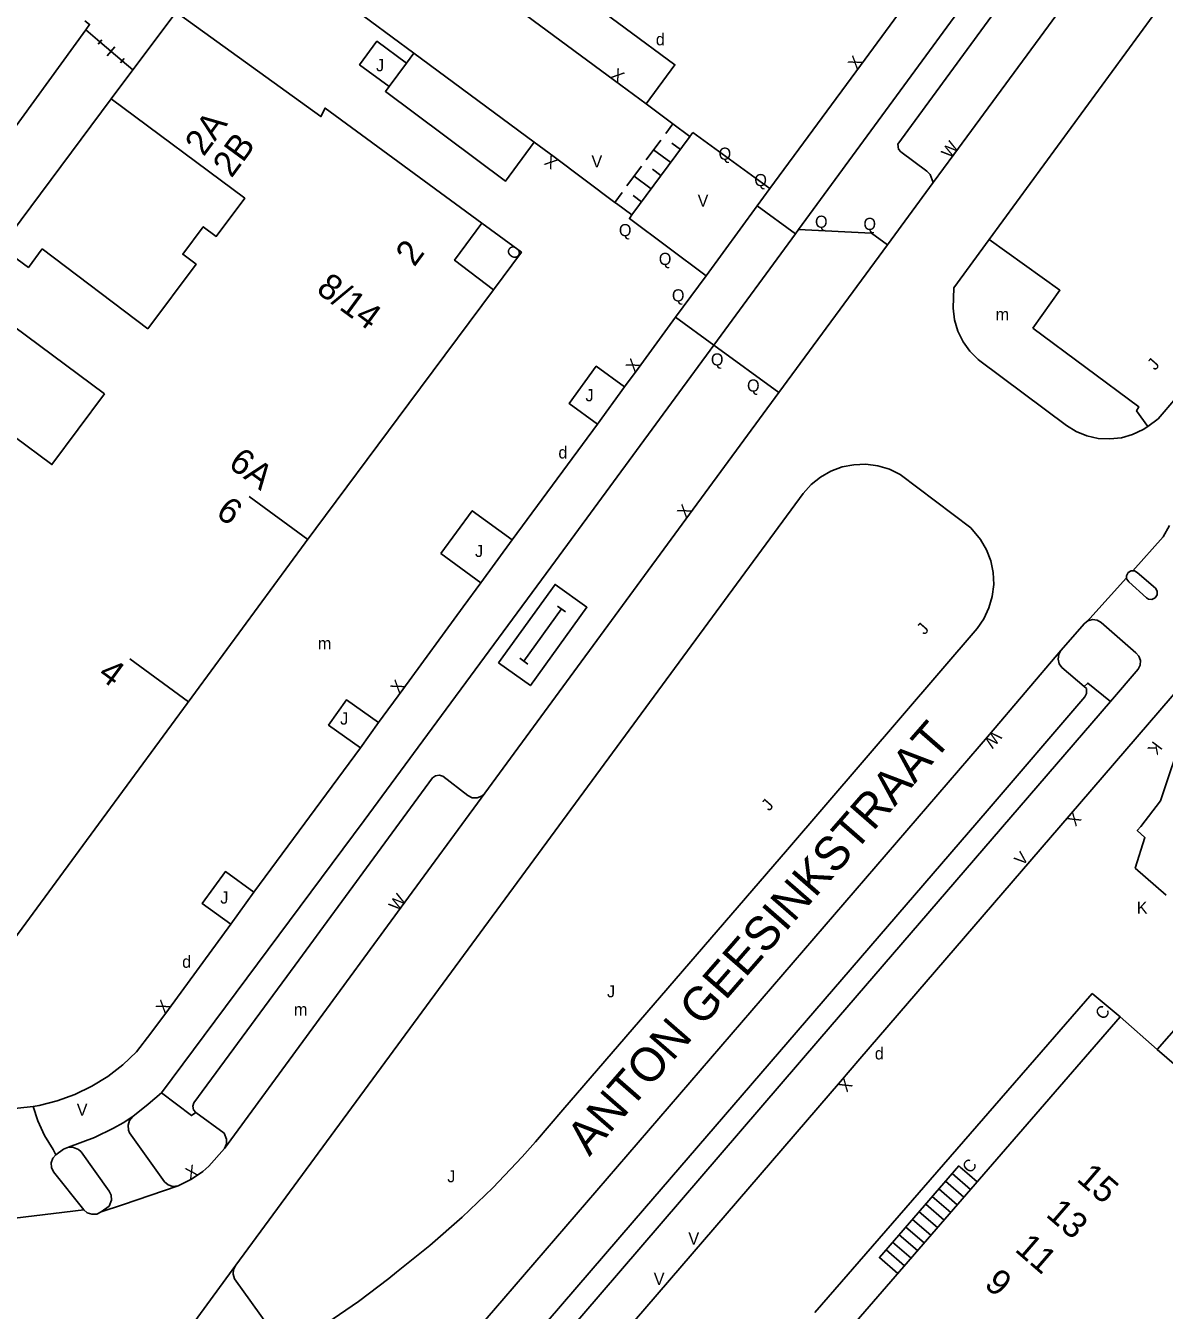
# Model space of a CAD drawing. Extents: x 134999 to 136502, y 457398 to 459002.
# Drawn here: x 135720.5 to 135767.4, y 457512.2 to 457565.2 of the extents above; entities that cross this region are included whole.
import ezdxf

# ---------------------------------------------------------------- set-up
doc = ezdxf.new("R2010")
doc.units = 0
for name, color, linetype in [('RI_DGTB_15', 7, 'Continuous'), ('RI_DGTB_2', 7, 'Continuous'), ('RI_DGTB_28', 7, 'Continuous'), ('RI_DGTB_29', 7, 'Continuous'), ('RI_DGTB_30', 7, 'Continuous'), ('RI_DGTB_31', 7, 'Continuous'), ('RI_DGTB_35', 7, 'Continuous'), ('RI_DGTB_36', 7, 'Continuous'), ('RI_DGTB_37', 7, 'Continuous'), ('RI_DGTB_4', 7, 'Continuous'), ('RI_DGTB_43', 7, 'Continuous'), ('RI_DGTB_5', 7, 'Continuous'), ('RI_DGTB_53', 7, 'Continuous'), ('RI_DGTB_54', 7, 'Continuous'), ('RI_DGTB_7', 7, 'Continuous')]:
    doc.layers.add(name, color=color, linetype=linetype)

msp = doc.modelspace()

# ---------------------------------------------------------------- linework, layer by layer
at = {"layer": 'RI_DGTB_15'}
for p, q in [((135732.135, 457543.982), (135729.717, 457545.758)), ((135727.224, 457537.291), (135724.806, 457539.067))]:
    msp.add_line(p, q, dxfattribs=at)
at = {"layer": 'RI_DGTB_2'}
for p, q in [((135753.03, 457512.108), (135764.454, 457525.27)), ((135764.454, 457525.27), (135765.613, 457524.299))]:
    msp.add_line(p, q, dxfattribs=at)
at = {"layer": 'RI_DGTB_28'}
for p, q in [((135759.018, 457518.107), (135759.403, 457517.774)), ((135758.418, 457517.524), (135759.175, 457516.869)), ((135758.69, 457517.839), (135759.447, 457517.184)), ((135759.72, 457517.499), (135759.403, 457517.774)), ((135757.873, 457516.895), (135758.63, 457516.24)), ((135758.146, 457517.209), (135758.903, 457516.554)), ((135757.601, 457516.58), (135758.358, 457515.925)), ((135757.056, 457515.95), (135757.813, 457515.295)), ((135757.329, 457516.265), (135758.086, 457515.61)), ((135756.512, 457515.321), (135757.269, 457514.666)), ((135756.784, 457515.636), (135757.541, 457514.981)), ((135756.239, 457515.006), (135756.996, 457514.351)), ((135755.967, 457514.691), (135756.724, 457514.036))]:
    msp.add_line(p, q, dxfattribs=at)
msp.add_lwpolyline([(135759.018, 457518.107), (135758.963, 457518.154), (135755.695, 457514.377), (135756.452, 457513.722)], dxfattribs=at)
at = {"layer": 'RI_DGTB_29'}
for points in [[(135740.001, 457538.897), (135741.308, 457537.956), (135743.637, 457541.189), (135742.331, 457542.13), (135740.001, 457538.897)], [(135742.432, 457541.239), (135742.759, 457541.003)], [(135742.596, 457541.121), (135741.043, 457538.965)], [(135740.879, 457539.083), (135741.206, 457538.847)]]:
    msp.add_lwpolyline(points, dxfattribs=at)
at = {"layer": 'RI_DGTB_31'}
for p, q in [((135746.887, 457560.72), (135747.186, 457561.125)), ((135745.494, 457557.363), (135747.889, 457560.606)), ((135746.088, 457559.639), (135746.687, 457560.449)), ((135747.49, 457560.065), (135747.138, 457560.325)), ((135747.091, 457559.525), (135746.388, 457560.044)), ((135745.29, 457558.558), (135745.889, 457559.368)), ((135746.692, 457558.984), (135746.34, 457559.244)), ((135746.292, 457558.444), (135745.589, 457558.963)), ((135744.791, 457557.882), (135745.09, 457558.287)), ((135745.893, 457557.903), (135745.542, 457558.163))]:
    msp.add_line(p, q, dxfattribs=at)
at = {"layer": 'RI_DGTB_4'}
for p, q in [((135713.171, 457551.48), (135722.984, 457564.989)), ((135736.3, 457549.585), (135739.791, 457554.28)), ((135732.032, 457543.842), (135736.3, 457549.585)), ((135727.509, 457537.683), (135732.032, 457543.842)), ((135723.518, 457532.249), (135727.509, 457537.683)), ((135719.868, 457527.278), (135723.518, 457532.249)), ((135754.198, 457511.12), (135765.613, 457524.299)), ((135767.14, 457522.962), (135782.876, 457509.177))]:
    msp.add_line(p, q, dxfattribs=at)
for points in [[(135724.932, 457563.348), (135726.706, 457565.729), (135732.68, 457561.421), (135732.852, 457561.77), (135739.309, 457557.028)], [(135722.984, 457564.989), (135723.148, 457565.215), (135722.943, 457565.366)], [(135739.791, 457554.28), (135738.189, 457555.496), (135739.309, 457557.028)], [(135739.309, 457557.028), (135740.942, 457555.828), (135739.791, 457554.28)], [(135765.613, 457524.299), (135767.14, 457522.962)]]:
    msp.add_lwpolyline(points, dxfattribs=at)
at = {"layer": 'RI_DGTB_5'}
for points in [[(135724.037, 457562.146), (135724.932, 457563.348)], [(135724.037, 457562.146), (135729.536, 457558.049), (135728.366, 457556.478), (135727.831, 457556.877), (135726.983, 457555.739), (135727.531, 457555.331), (135725.551, 457552.672)], [(135721.19, 457555.961), (135720.625, 457555.203), (135719.488, 457556.038)], [(135725.551, 457552.672), (135721.19, 457555.961)], [(135723.755, 457549.99), (135718.395, 457553.971)], [(135723.755, 457549.99), (135721.591, 457547.072), (135720.03, 457548.229), (135719.328, 457547.283), (135716.005, 457549.748), (135716.394, 457550.272), (135715.942, 457550.607)]]:
    msp.add_lwpolyline(points, dxfattribs=at)
at = {"layer": 'RI_DGTB_53'}
for p, q in [((135758.755, 457559.86), (135765.655, 457569.241)), ((135767.968, 457566.947), (135760.215, 457556.352)), ((135760.733, 457566.134), (135756.452, 457560.286)), ((135736.208, 457563.624), (135736.51, 457564.032)), ((135751.181, 457558.447), (135754.909, 457563.528)), ((135756.572, 457559.962), (135757.65, 457559.173)), ((135757.91, 457558.698), (135758.755, 457559.86)), ((135744.858, 457557.832), (135745.489, 457557.363)), ((135767.179, 457548.96), (135771.238, 457553.708)), ((135747.296, 457553.142), (135748.867, 457551.99)), ((135748.867, 457551.99), (135742.339, 457543.103)), ((135751.554, 457550.046), (135748.867, 457551.99)), ((135759.838, 457551.342), (135763.402, 457548.683)), ((135759.465, 457544.467), (135756.555, 457546.656)), ((135752.549, 457545.883), (135729.165, 457514.058)), ((135742.339, 457543.103), (135737.064, 457535.941)), ((135766.319, 457542.622), (135767.067, 457541.976)), ((135738.546, 457541.21), (135739.263, 457542.2)), ((135766.698, 457541.575), (135765.967, 457542.231)), ((135764.14, 457540.512), (135763.175, 457539.402)), ((135764.834, 457540.554), (135766.254, 457539.314)), ((135763.175, 457539.402), (135760.228, 457535.948)), ((135766.351, 457538.633), (135765.213, 457537.304)), ((135753.244, 457523.4), (135765.213, 457537.304)), ((135760.127, 457532.798), (135764.164, 457537.495)), ((135740.222, 457512.685), (135760.228, 457535.948)), ((135737.274, 457534.149), (135735.16, 457531.263)), ((135745.585, 457515.899), (135760.127, 457532.798)), ((135763.517, 457532.594), (135754.883, 457522.569)), ((135738.479, 457506.217), (135753.244, 457523.4)), ((135728.696, 457519.501), (135727.525, 457520.364)), ((135724.796, 457519.516), (135726.237, 457517.503)), ((135722.272, 457518.924), (135723.343, 457519.327)), ((135721.756, 457518.612), (135721.646, 457518.828)), ((135721.756, 457518.612), (135722.071, 457518.853)), ((135722.792, 457518.733), (135723.945, 457517.121)), ((135728.064, 457518.147), (135728.709, 457518.88)), ((135722.913, 457516.341), (135721.659, 457517.914)), ((135722.913, 457516.341), (135719.614, 457515.953)), ((135723.954, 457516.496), (135723.62, 457516.259)), ((135738.072, 457507.166), (135745.585, 457515.899)), ((135729.165, 457514.058), (135727.453, 457511.71)), ((135729.119, 457513.495), (135730.899, 457511.009))]:
    msp.add_line(p, q, dxfattribs=at)
for points in [[(135783.512, 457599.293), (135783.388, 457599.105), (135781.066, 457595.931), (135773.399, 457585.472), (135763.723, 457572.277), (135752.365, 457556.762)], [(135746.083, 457561.948), (135744.782, 457562.903), (135730.27, 457573.622), (135728.801, 457574.712)], [(135754.909, 457563.528), (135758.537, 457568.474)], [(135736.51, 457564.032), (135732.048, 457567.339)], [(135743.168, 457566.593), (135747.268, 457563.558), (135746.083, 457561.948)], [(135735.495, 457562.656), (135734.273, 457563.555), (135734.986, 457564.523), (135736.208, 457563.624)], [(135741.462, 457560.361), (135736.51, 457564.032)], [(135736.208, 457563.624), (135735.495, 457562.656)], [(135741.462, 457560.361), (135740.278, 457558.749), (135735.336, 457562.457), (135735.495, 457562.656)], [(135746.083, 457561.948), (135747.186, 457561.125)], [(135747.186, 457561.125), (135747.887, 457560.603), (135748.007, 457560.757)], [(135744.791, 457557.882), (135742.289, 457559.76), (135741.462, 457560.361)], [(135748.007, 457560.757), (135751.181, 457558.447)], [(135756.452, 457560.286), (135756.481, 457560.079), (135756.572, 457559.962)], [(135757.91, 457558.698), (135756.026, 457556.134)], [(135757.65, 457559.173), (135757.784, 457559.033), (135757.91, 457558.698)], [(135751.181, 457558.447), (135750.661, 457557.738)], [(135744.858, 457557.832), (135744.791, 457557.882)], [(135748.551, 457554.857), (135750.661, 457557.738)], [(135750.661, 457557.738), (135752.235, 457556.585)], [(135745.489, 457557.363), (135745.391, 457557.216), (135748.551, 457554.857)], [(135748.867, 457551.99), (135752.235, 457556.585)], [(135752.235, 457556.585), (135752.365, 457556.762)], [(135756.026, 457556.134), (135755.372, 457556.605), (135752.365, 457556.762)], [(135756.026, 457556.134), (135751.554, 457550.046)], [(135760.215, 457556.352), (135758.765, 457554.355)], [(135762.013, 457552.694), (135763.13, 457554.255), (135760.215, 457556.352)], [(135747.296, 457553.142), (135748.551, 457554.857)], [(135758.765, 457554.355), (135758.73, 457553.515), (135758.79, 457553.036), (135758.927, 457552.573), (135759.14, 457552.138), (135759.42, 457551.745), (135759.762, 457551.403), (135759.838, 457551.342)], [(135745.189, 457550.27), (135745.755, 457551.036), (135747.296, 457553.142)], [(135766.754, 457548.646), (135766.292, 457549.284), (135766.39, 457549.445), (135762.013, 457552.694)], [(135745.189, 457550.27), (135744.022, 457551.123), (135742.904, 457549.595), (135744.07, 457548.742)], [(135744.07, 457548.742), (135745.189, 457550.27)], [(135751.554, 457550.046), (135747.87, 457545.031), (135739.435, 457533.522)], [(135778.654, 457550.216), (135776.802, 457548.044), (135776.153, 457547.284), (135772.427, 457542.954), (135763.517, 457532.594)], [(135740.554, 457543.963), (135744.07, 457548.742)], [(135763.402, 457548.683), (135763.796, 457548.439), (135764.24, 457548.257), (135764.708, 457548.152), (135765.187, 457548.126), (135765.663, 457548.18), (135766.124, 457548.312), (135766.557, 457548.519), (135766.754, 457548.646)], [(135766.754, 457548.646), (135767.179, 457548.96)], [(135756.555, 457546.656), (135756.106, 457546.875), (135755.631, 457547.018), (135755.14, 457547.082), (135754.645, 457547.067), (135754.159, 457546.972), (135753.695, 457546.801), (135753.264, 457546.557), (135752.878, 457546.247), (135752.549, 457545.883)], [(135737.62, 457543.402), (135738.911, 457545.166), (135740.554, 457543.963)], [(135759.72, 457540.314), (135759.997, 457540.715), (135760.209, 457541.16), (135760.346, 457541.634), (135760.406, 457542.124), (135760.385, 457542.617), (135760.285, 457543.101), (135760.109, 457543.562), (135759.86, 457543.988), (135759.465, 457544.467)], [(135767.644, 457544.553), (135767.384, 457544.095), (135766.134, 457542.689)], [(135740.554, 457543.963), (135739.263, 457542.2)], [(135739.263, 457542.2), (135737.62, 457543.402)], [(135765.881, 457542.405), (135764.368, 457540.728), (135764.14, 457540.512)], [(135765.881, 457542.405), (135765.875, 457542.488), (135765.941, 457542.616), (135766.064, 457542.69), (135766.134, 457542.689)], [(135765.967, 457542.231), (135765.885, 457542.344), (135765.881, 457542.405)], [(135766.134, 457542.689), (135766.208, 457542.688), (135766.319, 457542.622)], [(135767.067, 457541.976), (135767.139, 457541.846), (135767.134, 457541.7), (135767.054, 457541.577), (135766.923, 457541.514), (135766.777, 457541.528), (135766.698, 457541.575)], [(135738.546, 457541.21), (135736.05, 457537.795), (135735.049, 457536.434)], [(135741.514, 457519.143), (135742.648, 457520.469), (135751.904, 457531.206), (135759.72, 457540.314)], [(135764.14, 457540.512), (135764.288, 457540.634), (135764.474, 457540.686), (135764.665, 457540.66), (135764.829, 457540.559), (135764.834, 457540.554)], [(135763.217, 457538.707), (135763.102, 457538.86), (135763.053, 457539.053), (135763.084, 457539.249), (135763.175, 457539.402)], [(135766.254, 457539.314), (135766.387, 457539.175), (135766.453, 457538.995), (135766.44, 457538.803), (135766.351, 457538.633)], [(135764.134, 457537.917), (135763.217, 457538.707)], [(135765.213, 457537.304), (135764.277, 457538.061), (135764.134, 457537.917)], [(135764.222, 457537.841), (135764.134, 457537.917)], [(135764.164, 457537.495), (135764.233, 457537.63), (135764.222, 457537.841)], [(135734.312, 457535.394), (135732.994, 457536.328), (135733.73, 457537.368), (135735.049, 457536.434)], [(135726.115, 457521.169), (135734.462, 457532.398), (135737.064, 457535.941)], [(135735.049, 457536.434), (135734.312, 457535.394)], [(135734.312, 457535.394), (135729.92, 457529.446)], [(135737.708, 457534.218), (135737.554, 457534.268), (135737.394, 457534.24), (135737.274, 457534.149)], [(135737.708, 457534.218), (135738.735, 457533.424)], [(135728.709, 457518.88), (135735.987, 457528.828), (135739.435, 457533.522)], [(135738.735, 457533.424), (135738.912, 457533.337), (135739.11, 457533.326), (135739.296, 457533.394), (135739.435, 457533.522)], [(135727.444, 457520.761), (135731.616, 457526.433), (135735.16, 457531.263)], [(135728.969, 457528.125), (135727.791, 457528.974), (135728.741, 457530.294), (135729.92, 457529.446)], [(135729.92, 457529.446), (135728.969, 457528.125)], [(135728.969, 457528.125), (135726.391, 457524.598), (135725.662, 457523.633), (135725.073, 457522.855)], [(135791.57, 457501.88), (135791.726, 457502.039), (135787.785, 457508.039), (135768.723, 457524.758), (135767.14, 457522.962)], [(135725.073, 457522.855), (135724.512, 457522.321), (135723.899, 457521.848), (135723.24, 457521.441), (135722.543, 457521.104), (135721.815, 457520.84), (135721.063, 457520.653), (135720.819, 457520.609)], [(135754.883, 457522.569), (135754.086, 457521.634), (135744.67, 457510.688), (135738.014, 457502.923), (135735.404, 457499.919)], [(135726.115, 457521.169), (135725.559, 457520.699), (135724.924, 457520.194)], [(135727.525, 457520.364), (135727.348, 457520.23), (135726.115, 457521.169)], [(135720.819, 457520.609), (135720.183, 457520.534), (135719.446, 457520.522), (135718.712, 457520.589), (135717.989, 457520.736), (135717.329, 457520.944)], [(135721.646, 457518.828), (135721.29, 457519.407), (135721.013, 457520.009), (135720.819, 457520.609)], [(135727.525, 457520.364), (135727.427, 457520.473), (135727.396, 457520.62), (135727.444, 457520.761)], [(135723.343, 457519.327), (135724.13, 457519.709), (135724.525, 457519.936), (135724.924, 457520.194)], [(135724.924, 457520.194), (135724.795, 457520.035), (135724.733, 457519.836), (135724.75, 457519.628), (135724.796, 457519.516)], [(135728.709, 457518.88), (135728.79, 457519.064), (135728.793, 457519.263), (135728.696, 457519.501)], [(135735.797, 457513.782), (135737.17, 457514.88), (135738.492, 457516.039), (135739.76, 457517.257), (135740.971, 457518.531), (135741.514, 457519.143)], [(135721.659, 457517.914), (135721.574, 457518.089), (135721.563, 457518.287), (135721.631, 457518.473), (135721.756, 457518.612)], [(135722.071, 457518.853), (135722.272, 457518.924)], [(135722.272, 457518.924), (135722.486, 457518.916), (135722.681, 457518.831), (135722.792, 457518.733)], [(135726.792, 457517.332), (135727.343, 457517.606), (135727.809, 457517.927), (135728.064, 457518.147)], [(135726.237, 457517.503), (135726.385, 457517.375), (135726.574, 457517.313), (135726.792, 457517.332)], [(135723.62, 457516.259), (135724.497, 457516.547), (135726.792, 457517.332)], [(135723.945, 457517.121), (135724.033, 457516.944), (135724.044, 457516.747), (135723.954, 457516.496)], [(135723.62, 457516.259), (135723.438, 457516.172), (135723.236, 457516.161), (135723.045, 457516.228), (135722.913, 457516.341)], [(135729.165, 457514.058), (135729.072, 457513.884), (135729.055, 457513.687), (135729.119, 457513.495)], [(135731.582, 457510.85), (135732.923, 457511.672), (135734.22, 457512.561), (135735.47, 457513.515), (135735.797, 457513.782)], [(135736.187, 457508.018), (135736.346, 457508.196), (135740.222, 457512.685)]]:
    msp.add_lwpolyline(points, dxfattribs=at)
at = {"layer": 'RI_DGTB_54'}
for p, q in [((135722.984, 457564.989), (135723.57, 457564.496)), ((135723.647, 457564.588), (135723.492, 457564.405)), ((135724.489, 457563.722), (135723.57, 457564.496)), ((135724.489, 457563.722), (135723.57, 457564.496)), ((135724.184, 457564.293), (135723.875, 457563.926)), ((135724.566, 457563.814), (135724.412, 457563.63)), ((135724.932, 457563.348), (135724.489, 457563.722))]:
    msp.add_line(p, q, dxfattribs=at)
for points in [[(135767.513, 457529.316), (135766.234, 457530.434), (135766.634, 457531.692), (135766.316, 457531.983), (135766.465, 457532.145), (135767.279, 457533.21), (135768.237, 457536.077), (135770.444, 457538.597), (135771.104, 457539.283), (135772.639, 457541.137), (135773.375, 457541.944), (135777.486, 457546.732), (135778.158, 457547.456), (135779.788, 457549.425), (135780.486, 457550.168), (135784.546, 457554.899), (135787.528, 457558.334), (135791.562, 457563.091), (135792.26, 457563.872), (135793.058, 457564.833)], [(135719.488, 457556.038), (135724.037, 457562.146)]]:
    msp.add_lwpolyline(points, dxfattribs=at)

# ---------------------------------------------------------------- texts
at = {"layer": 'RI_DGTB_29'}
for p in [(135746.481, 457564.355), (135742.464, 457547.321), (135726.96, 457526.324), (135755.504, 457522.544)]:
    msp.add_text('d', height=0.5, dxfattribs=at).set_placement(p)
at = {"layer": 'RI_DGTB_30'}
for s, rotation, p in [('X', 53.8678, (135754.762, 457563.326)), ('X', 323.4196, (135744.581, 457563.052)), ('W', 53.9156, (135758.608, 457559.658)), ('X', 143.1056, (135742.489, 457559.61)), ('X', 53.559, (135745.607, 457550.835)), ('X', 53.7004, (135747.722, 457544.83)), ('X', 53.8411, (135735.902, 457537.593)), ('W', 229.5288, (135760.39, 457536.138)), ('K', 232.5495, (135766.99, 457535.707)), ('X', 229.3064, (135763.68, 457532.784)), ('V', 49.3985, (135761.587, 457530.497)), ('W', 53.8127, (135735.839, 457528.626)), ('X', 53.961, (135726.244, 457524.396)), ('X', 229.5767, (135754.248, 457521.824)), ('X', 27.625, (135727.266, 457517.58))]:
    msp.add_text(s, height=0.5, rotation=rotation, dxfattribs=at).set_placement(p)
for s, p in [('V', (135743.826, 457559.32)), ('V', (135748.201, 457557.705)), ('K', (135766.296, 457528.557)), ('V', (135722.615, 457520.226)), ('V', (135747.82, 457514.912)), ('V', (135746.392, 457513.252))]:
    msp.add_text(s, height=0.5, dxfattribs=at).set_placement(p)
at = {"layer": 'RI_DGTB_31'}
for s, p in [('J', (135734.95, 457563.286)), ('Q', (135749.066, 457559.639)), ('Q', (135750.539, 457558.551)), ('Q', (135753.038, 457556.834)), ('Q', (135755.034, 457556.744)), ('Q', (135744.957, 457556.487)), ('Q', (135746.602, 457555.301)), ('Q', (135747.142, 457553.797)), ('Q', (135748.748, 457551.156)), ('Q', (135750.237, 457550.079)), ('J', (135744.467, 457525.107)), ('J', (135737.884, 457517.48))]:
    msp.add_text(s, height=0.5, dxfattribs=at).set_placement(p)
for height, rotation, p in [(0.499, 48.8553, (135767.055, 457550.927)), (0.5, 359.9996, (135743.58, 457549.68)), (0.5, 359.9996, (135739.03, 457543.26)), (0.499, 48.8553, (135757.554, 457540.023)), (0.5, 359.9996, (135733.47, 457536.35)), (0.499, 48.8553, (135751.153, 457532.757)), (0.5, 359.9996, (135728.53, 457528.97))]:
    msp.add_text('J', height=height, rotation=rotation, dxfattribs=at).set_placement(p)
at = {"layer": 'RI_DGTB_35'}
for s, rotation, p in [('2A', 53.6985, (135727.844, 457559.74)), ('2', 53.6985, (135736.526, 457555.189)), ('8/14', 323.7307, (135732.439, 457554.198)), ('15', 319.1116, (135763.776, 457517.564)), ('9', 319.1041, (135759.968, 457513.211))]:
    msp.add_text(s, height=1.054, rotation=rotation, dxfattribs=at).set_placement(p)
at = {"layer": 'RI_DGTB_36'}
for s, rotation, p in [('2B', 53.6985, (135728.992, 457558.854)), ('6A', 323.7307, (135728.813, 457546.997)), ('6', 323.7214, (135728.297, 457544.98)), ('4', 323.7214, (135723.438, 457538.319)), ('13', 319.1041, (135762.511, 457516.106)), ('11', 319.1116, (135761.231, 457514.67))]:
    msp.add_text(s, height=1.054, rotation=rotation, dxfattribs=at).set_placement(p)
at = {"layer": 'RI_DGTB_37'}
msp.add_text('ANTON GEESINKSTRAAT', height=1.4, rotation=48.915, dxfattribs=at).set_placement((135743.742, 457518.518))
at = {"layer": 'RI_DGTB_43'}
for p in [(135760.482, 457553.015), (135732.551, 457539.448), (135731.565, 457524.357)]:
    msp.add_text('m', height=0.5, dxfattribs=at).set_placement(p)
at = {"layer": 'RI_DGTB_7'}
for rotation, p in [(52.9116, (135740.673, 457555.473)), (48.4043, (135764.909, 457524.142)), (48.4043, (135759.429, 457517.814))]:
    msp.add_text('C', height=0.5, rotation=rotation, dxfattribs=at).set_placement(p)

doc.saveas('drawing.dxf')
